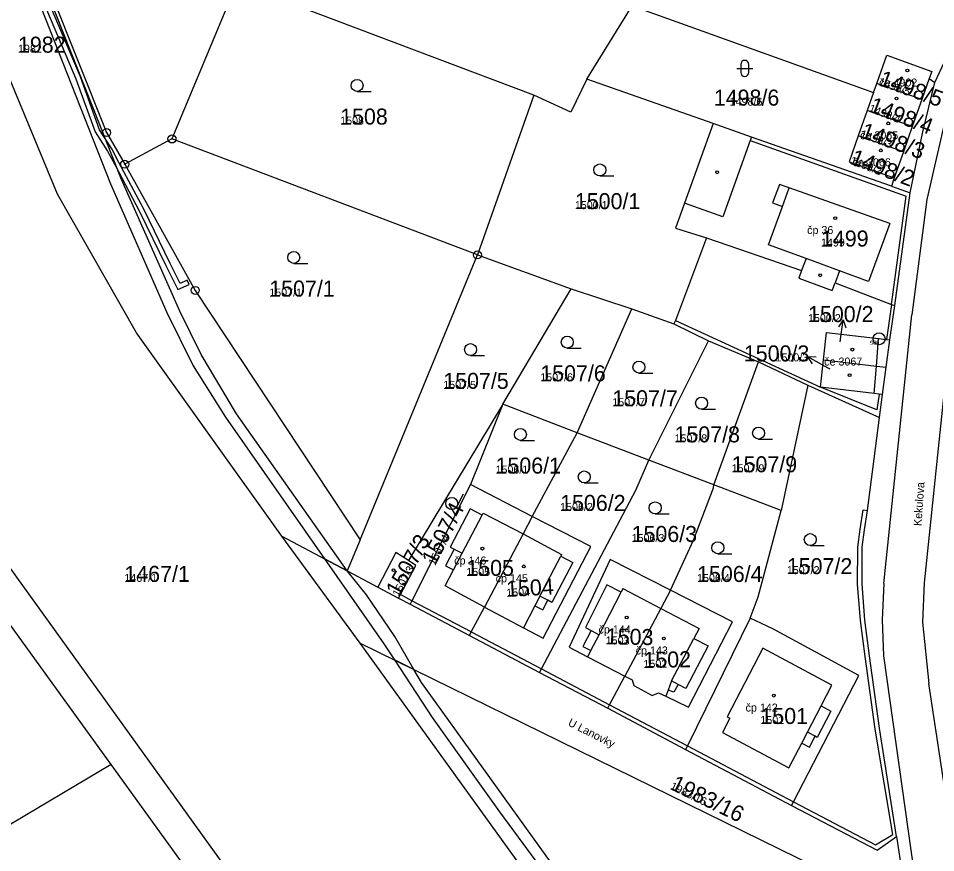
# Model space of a CAD drawing. Extents: x -763628 to -761565, y -976033 to -973833.
# Drawn here: x -762844 to -762729.4, y -975688.4 to -975584.1 of the extents above; entities that cross this region are included whole.
import ezdxf

# ---------------------------------------------------------------- set-up
doc = ezdxf.new("R2010")
doc.units = 0
for name, color, linetype in [('KN_cisla parcel 1000', 7, 'Continuous'), ('KN_cisla parcel 500', 7, 'Continuous'), ('KN_cisla parcel znacky', 7, 'Continuous'), ('KN_cisla popisna 500', 7, 'Continuous'), ('KN_hranice parcel', 7, 'Continuous'), ('KN_popisy', 7, 'Continuous'), ('KN_vecna bremena', 7, 'Continuous'), ('KN_vnitrni kresba parcel', 7, 'Continuous'), ('KN_znacky bodu BP', 7, 'Continuous'), ('KN_znacky budov', 7, 'Continuous'), ('KN_znacky kultur', 7, 'Continuous')]:
    doc.layers.add(name, color=color, linetype=linetype)

msp = doc.modelspace()

# ---------------------------------------------------------------- linework, layer by layer
at = {"layer": 'KN_cisla parcel znacky'}
for p, q in [((-762740.96, -975621.78), (-762741.54, -975622.62)), ((-762741.34, -975624.51), (-762740.96, -975621.78)), ((-762740.96, -975621.78), (-762740.63, -975622.75)), ((-762742.84, -975627.81), (-762745.47, -975626.36)), ((-762745.47, -975626.36), (-762744.35, -975626.4)), ((-762745.47, -975626.36), (-762744.83, -975627.28)), ((-762742.6, -975627.94), (-762742.84, -975627.81))]:
    msp.add_line(p, q, dxfattribs=at)
at = {"layer": 'KN_hranice parcel'}
for p, q in [((-762773, -975591.7), (-762767.32, -975582.5)), ((-762757.22, -975597.21), (-762773, -975591.7)), ((-762737.17, -975593.36), (-762736.77, -975592.23)), ((-762731.13, -975594.22), (-762736.77, -975592.23)), ((-762779.62, -975593.67), (-762786.67, -975613.65)), ((-762737.17, -975593.36), (-762737.96, -975595.6)), ((-762731.13, -975594.22), (-762732.33, -975597.59)), ((-762737.96, -975595.6), (-762739.08, -975598.78)), ((-762732.33, -975597.59), (-762737.96, -975595.6)), ((-762732.33, -975597.59), (-762733.45, -975600.77)), ((-762733.45, -975600.77), (-762739.08, -975598.78)), ((-762824.82, -975599.16), (-762830.73, -975602.32)), ((-762786.67, -975613.65), (-762824.82, -975599.16)), ((-762733.45, -975600.77), (-762734.59, -975604)), ((-762734.59, -975604), (-762734.95, -975605.07)), ((-762734.95, -975605.07), (-762732.6, -975605.9)), ((-762734.52, -975619.97), (-762732.6, -975605.9)), ((-762801.32, -975649.26), (-762786.67, -975613.65)), ((-762786.67, -975613.65), (-762774.97, -975617.89)), ((-762783.49, -975632.31), (-762774.97, -975617.89)), ((-762774.97, -975617.89), (-762767.36, -975620.39)), ((-762774.19, -975635.87), (-762767.36, -975620.39)), ((-762735.12, -975624.27), (-762734.52, -975619.97)), ((-762735.58, -975627.68), (-762735.12, -975624.27)), ((-762765.26, -975639.29), (-762757.79, -975624.4)), ((-762757.79, -975624.4), (-762751.56, -975627.01)), ((-762757.13, -975642.4), (-762751.56, -975627.01)), ((-762751.56, -975627.01), (-762745.39, -975629.93)), ((-762736.05, -975631.11), (-762735.58, -975627.68)), ((-762745.39, -975629.93), (-762748.73, -975645.61)), ((-762745.39, -975629.93), (-762736.44, -975633.97)), ((-762736.44, -975633.97), (-762736.05, -975631.11)), ((-762783.49, -975632.31), (-762795.29, -975651.85)), ((-762783.49, -975632.31), (-762787.53, -975642.34)), ((-762774.19, -975635.87), (-762783.49, -975632.31)), ((-762779.82, -975646.33), (-762774.19, -975635.87)), ((-762765.26, -975639.29), (-762774.19, -975635.87)), ((-762757.13, -975642.4), (-762765.26, -975639.29)), ((-762779.82, -975646.33), (-762787.53, -975642.34)), ((-762748.73, -975645.61), (-762757.13, -975642.4)), ((-762811.1, -975648.8), (-762802.92, -975653.15)), ((-762801.33, -975662.17), (-762811.1, -975648.8)), ((-762801.32, -975649.26), (-762802.92, -975653.15)), ((-762802.92, -975653.15), (-762799.12, -975655.17)), ((-762799.12, -975655.17), (-762796.51, -975656.55)), ((-762832.43, -975677.34), (-762847.47, -975656.53)), ((-762796.51, -975656.55), (-762795.06, -975657.31)), ((-762795.06, -975657.31), (-762787.66, -975661.21)), ((-762787.66, -975661.21), (-762778.9, -975665.83)), ((-762757.25, -975723.26), (-762801.33, -975662.17)), ((-762778.9, -975665.83), (-762770.38, -975670.32)), ((-762770.38, -975670.32), (-762760.65, -975675.46)), ((-762760.65, -975675.46), (-762747.41, -975682.45)), ((-762820.54, -975693.78), (-762832.43, -975677.34)), ((-762734.3, -975686.33), (-762732.8, -975696.41))]:
    msp.add_line(p, q, dxfattribs=at)
for points in [[(-762732.6, -975605.9), (-762731.03, -975598.28), (-762729.5, -975592.1), (-762728.34, -975589.62), (-762719.64, -975571.02), (-762714.08, -975552.67), (-762709.55, -975545.05), (-762703.62, -975531.5)], [(-762856.31, -975534.48), (-762857.3, -975537.42), (-762833, -975598.35), (-762830.73, -975602.32)], [(-762777.26, -975743.54), (-762778.83, -975742.17), (-762779.94, -975743.26), (-762853.85, -975640.55), (-762917.53, -975553.11), (-762915.39, -975552.59), (-762916.08, -975550.64)], [(-762811.1, -975648.8), (-762829.27, -975623.41), (-762839.12, -975606.05), (-762852.52, -975573.73)], [(-762779.62, -975593.67), (-762816.73, -975579.64), (-762824.82, -975599.16)], [(-762767.32, -975582.5), (-762760.11, -975585.08), (-762737.17, -975593.36)], [(-762736.77, -975592.23), (-762735.51, -975588.69), (-762729.9, -975590.73), (-762730.24, -975591.58), (-762731.13, -975594.22)], [(-762773, -975591.7), (-762774.99, -975595.79), (-762779.62, -975593.67)], [(-762757.22, -975597.21), (-762760.8, -975607.17), (-762761.92, -975610.3), (-762758.06, -975611.52), (-762746.16, -975615.6), (-762746.51, -975616.56), (-762742.33, -975618.1), (-762741.98, -975617.14), (-762734.95, -975619.83), (-762734.52, -975619.97)], [(-762734.95, -975605.07), (-762752.43, -975598.93), (-762757.22, -975597.21)], [(-762739.08, -975598.78), (-762740.22, -975602.01), (-762734.59, -975604)], [(-762830.73, -975602.32), (-762821.91, -975618.09), (-762801.32, -975649.26)], [(-762767.36, -975620.39), (-762762.11, -975622.25), (-762757.79, -975624.4)], [(-762743.43, -975626.77), (-762743.07, -975623.36), (-762736.54, -975624.11), (-762735.55, -975624.22), (-762735.12, -975624.27)], [(-762736.05, -975631.11), (-762736.49, -975631.06), (-762737.09, -975630.98), (-762743.79, -975630.18), (-762743.43, -975626.77)], [(-762743.43, -975626.77), (-762736.81, -975627.54), (-762735.58, -975627.68)], [(-762734.3, -975686.33), (-762736.42, -975672.82), (-762737.66, -975663.78), (-762738.26, -975659.29), (-762738.61, -975654.77), (-762738.59, -975650.16), (-762738.3, -975648.01), (-762737.95, -975645.58), (-762736.44, -975633.97)], [(-762778.9, -975665.83), (-762778.67, -975665.39), (-762766.88, -975643.06), (-762765.26, -975639.29)], [(-762787.53, -975642.34), (-762794.84, -975656.87), (-762795.06, -975657.31)], [(-762762.54, -975655.55), (-762759.68, -975649.32), (-762757.17, -975642.75), (-762757.13, -975642.4)], [(-762752.57, -975659.04), (-762751.6, -975656.39), (-762748.73, -975645.61)], [(-762779.82, -975646.33), (-762780.96, -975648.52), (-762785.76, -975657.66)], [(-762785.76, -975657.66), (-762780.89, -975660.25), (-762778.43, -975661.56), (-762772.51, -975650.11), (-762779.82, -975646.33)], [(-762795.29, -975651.85), (-762796.84, -975650.85), (-762799.12, -975655.17)], [(-762762.54, -975655.55), (-762770.06, -975651.71), (-762775.22, -975662.67), (-762772.91, -975663.87), (-762768.24, -975666.3)], [(-762796.51, -975656.55), (-762796.28, -975656.11), (-762794.35, -975652.46), (-762795.29, -975651.85)], [(-762768.24, -975666.3), (-762767.33, -975666.77), (-762767.13, -975667.49), (-762764.84, -975668.72), (-762764.03, -975668.37), (-762763.14, -975668.8), (-762760.31, -975670.18), (-762754.78, -975659.52), (-762762.54, -975655.55)], [(-762762.54, -975655.55), (-762763.75, -975657.84), (-762768.24, -975666.3)], [(-762787.66, -975661.21), (-762787.43, -975660.77), (-762785.76, -975657.66)], [(-762752.57, -975659.04), (-762760.42, -975675.01), (-762760.65, -975675.46)], [(-762747.41, -975682.45), (-762747.17, -975682.01), (-762739, -975666.23), (-762749.74, -975660.38), (-762752.57, -975659.04)], [(-762801.33, -975662.17), (-762794.59, -975665.48), (-762742.09, -975691.25)], [(-762770.38, -975670.32), (-762770.15, -975669.88), (-762768.24, -975666.3)], [(-762832.43, -975677.34), (-762846.27, -975685.61), (-762854.67, -975690.74), (-762863.95, -975696.17)], [(-762747.41, -975682.45), (-762736.73, -975688.07), (-762734.3, -975686.33)]]:
    msp.add_lwpolyline(points, dxfattribs=at)
at = {"layer": 'KN_vecna bremena'}
for points in [[(-762846.61, -975570.58), (-762843.88, -975575.86), (-762832.49, -975604.76), (-762825.46, -975620.86), (-762822.16, -975627.52), (-762818.12, -975633.95), (-762805.77, -975651.64), (-762802.92, -975653.15), (-762816.74, -975633.5), (-762821.17, -975626.08), (-762823.86, -975620.67), (-762831.14, -975604.24), (-762841.95, -975576.87), (-762843.4, -975573.8), (-762848.49, -975565.08)], [(-762844.93, -975571.69), (-762843.04, -975576.63), (-762840.81, -975582.19), (-762836.83, -975591.63), (-762834.41, -975598.27), (-762832.86, -975600.68), (-762831.96, -975602.36), (-762828.86, -975608.23), (-762825.6, -975614.97), (-762824.08, -975617.99), (-762822.68, -975617.35), (-762822.93, -975616.8), (-762823.8, -975617.21), (-762825.06, -975614.71), (-762828.32, -975607.95), (-762831.44, -975602.08), (-762832.34, -975600.38), (-762833.87, -975598.01), (-762836.27, -975591.41), (-762840.25, -975581.97), (-762842.48, -975576.41), (-762844.51, -975571.09)]]:
    msp.add_lwpolyline(points, dxfattribs=at)
for points in [[(-762797.03, -975664.28), (-762794.59, -975665.48), (-762797, -975661.33), (-762800.52, -975656.14), (-762802.92, -975653.15), (-762805.77, -975651.64), (-762798.35, -975662.26)], [(-762797.03, -975664.28), (-762792.31, -975671.49), (-762783.9, -975683.27), (-762759.91, -975715.83), (-762757.15, -975720.53), (-762756.64, -975723.08), (-762756.93, -975723.71), (-762756.65, -975724.13), (-762755.82, -975722.26), (-762755.51, -975721.15), (-762756.19, -975719.29), (-762759.18, -975714.08), (-762778.08, -975688.75), (-762793.65, -975667.11), (-762794.59, -975665.48)]]:
    msp.add_lwpolyline(points, close=True, dxfattribs=at)
at = {"layer": 'KN_vnitrni kresba parcel'}
for p, q in [((-762726.73, -975590.15), (-762730.51, -975606.74)), ((-762730.24, -975591.58), (-762729.5, -975592.1)), ((-762752.43, -975598.93), (-762752.58, -975599.35)), ((-762752.58, -975599.35), (-762756.02, -975608.91)), ((-762752.58, -975599.35), (-762733.11, -975606.29)), ((-762748.93, -975604.84), (-762749.78, -975607.14)), ((-762747.71, -975605.27), (-762748.93, -975604.84)), ((-762748.53, -975607.58), (-762747.71, -975605.27)), ((-762735.13, -975609.74), (-762747.71, -975605.27)), ((-762734.95, -975619.83), (-762733.11, -975606.29)), ((-762730.51, -975606.74), (-762732.39, -975621.12)), ((-762756.02, -975608.91), (-762760.8, -975607.17)), ((-762750.31, -975612.37), (-762748.53, -975607.58)), ((-762749.78, -975607.14), (-762748.53, -975607.58)), ((-762735.13, -975609.74), (-762737.79, -975616.98)), ((-762758.06, -975611.52), (-762761.93, -975621.84)), ((-762745.6, -975614.1), (-762750.31, -975612.37)), ((-762745.6, -975614.1), (-762746.16, -975615.6)), ((-762741.43, -975615.64), (-762745.6, -975614.1)), ((-762741.43, -975615.64), (-762741.98, -975617.14)), ((-762737.79, -975616.98), (-762741.43, -975615.64)), ((-762734.95, -975619.83), (-762735.55, -975624.22)), ((-762761.93, -975621.84), (-762762.11, -975622.25)), ((-762761.93, -975621.84), (-762743.79, -975630.18)), ((-762735.88, -975654.72), (-762732.39, -975621.12)), ((-762727.34, -975621.05), (-762730.83, -975654.64)), ((-762736.81, -975627.54), (-762736.54, -975624.11)), ((-762737.09, -975630.98), (-762736.81, -975627.54)), ((-762736.76, -975633.02), (-762743.79, -975630.18)), ((-762736.49, -975631.06), (-762736.76, -975633.02)), ((-762787.58, -975645.39), (-762790.07, -975650.16)), ((-762786.07, -975646.17), (-762787.58, -975645.39)), ((-762786.07, -975646.17), (-762785.94, -975645.93)), ((-762785.94, -975645.93), (-762780.96, -975648.52)), ((-762738.84, -975647.94), (-762738.49, -975645.5)), ((-762738.49, -975645.5), (-762737.95, -975645.58)), ((-762788.55, -975650.95), (-762786.07, -975646.17)), ((-762739.14, -975650.17), (-762738.84, -975647.94)), ((-762780.96, -975648.52), (-762776.14, -975651.08)), ((-762789.55, -975650.43), (-762790.63, -975652.5)), ((-762790.07, -975650.16), (-762789.55, -975650.43)), ((-762789.55, -975650.43), (-762788.55, -975650.95)), ((-762739.16, -975654.79), (-762739.14, -975650.17)), ((-762789.63, -975653.03), (-762788.55, -975650.95)), ((-762778.85, -975656.31), (-762776.26, -975651.31)), ((-762776.14, -975651.08), (-762776.26, -975651.31)), ((-762776.26, -975651.31), (-762774.76, -975652.09)), ((-762790.63, -975652.5), (-762789.63, -975653.03)), ((-762774.76, -975652.09), (-762777.36, -975657.09)), ((-762790.7, -975655.03), (-762789.63, -975653.03)), ((-762785.76, -975657.66), (-762790.7, -975655.03)), ((-762770.51, -975654.88), (-762773.17, -975660.23)), ((-762768.72, -975655.81), (-762770.51, -975654.88)), ((-762738.81, -975659.34), (-762739.16, -975654.79)), ((-762735.88, -975654.72), (-762736.1, -975659.26)), ((-762730.83, -975654.64), (-762731.05, -975659.56)), ((-762794.84, -975656.87), (-762796.28, -975656.11)), ((-762778.85, -975656.31), (-762779.47, -975657.51)), ((-762777.87, -975656.82), (-762778.85, -975656.31)), ((-762771.47, -975661.12), (-762768.72, -975655.81)), ((-762768.48, -975655.35), (-762768.72, -975655.81)), ((-762768.48, -975655.35), (-762763.75, -975657.84)), ((-762787.43, -975660.77), (-762794.84, -975656.87)), ((-762779.47, -975657.51), (-762780.89, -975660.25)), ((-762779.47, -975657.51), (-762778.49, -975658.01)), ((-762778.49, -975658.01), (-762777.87, -975656.82)), ((-762777.36, -975657.09), (-762777.87, -975656.82)), ((-762763.75, -975657.84), (-762758.97, -975660.35)), ((-762738.21, -975663.85), (-762738.81, -975659.34)), ((-762736.1, -975659.26), (-762735.92, -975663.75)), ((-762731.05, -975659.56), (-762730.28, -975667.23)), ((-762787.43, -975660.77), (-762778.67, -975665.39)), ((-762772.44, -975660.61), (-762773.48, -975662.58)), ((-762773.17, -975660.23), (-762772.44, -975660.61)), ((-762772.44, -975660.61), (-762771.47, -975661.12)), ((-762758.97, -975660.35), (-762759.62, -975661.59)), ((-762772.5, -975663.09), (-762771.47, -975661.12)), ((-762762.41, -975666.9), (-762759.62, -975661.59)), ((-762759.62, -975661.59), (-762757.84, -975662.52)), ((-762773.48, -975662.58), (-762772.5, -975663.09)), ((-762772.5, -975663.09), (-762772.91, -975663.87)), ((-762757.84, -975662.52), (-762760.62, -975667.84)), ((-762751.01, -975662.82), (-762755.46, -975671.4)), ((-762742.39, -975667.42), (-762751.01, -975662.82)), ((-762736.96, -975672.91), (-762738.21, -975663.85)), ((-762735.92, -975663.75), (-762729.86, -975706.89)), ((-762778.67, -975665.39), (-762770.15, -975669.88)), ((-762762.41, -975666.9), (-762762.85, -975668.04)), ((-762761.6, -975667.33), (-762762.41, -975666.9)), ((-762761.6, -975667.33), (-762762.11, -975668.31)), ((-762760.62, -975667.84), (-762761.6, -975667.33)), ((-762743.73, -975670.01), (-762742.39, -975667.42)), ((-762722.28, -975720.1), (-762730.28, -975667.23)), ((-762762.85, -975668.04), (-762763.14, -975668.8)), ((-762762.11, -975668.31), (-762762.85, -975668.04)), ((-762770.15, -975669.88), (-762760.42, -975675.01)), ((-762745.44, -975673.31), (-762743.73, -975670.01)), ((-762743.73, -975670.01), (-762742.49, -975670.66)), ((-762742.49, -975670.66), (-762744.2, -975673.95)), ((-762755.12, -975671.57), (-762756.06, -975673.34)), ((-762755.46, -975671.4), (-762755.12, -975671.57)), ((-762756.06, -975673.34), (-762747.74, -975677.75)), ((-762746.14, -975674.66), (-762745.44, -975673.31)), ((-762744.46, -975673.81), (-762745.44, -975673.31)), ((-762734.76, -975686.09), (-762736.96, -975672.91)), ((-762747.74, -975677.75), (-762746.14, -975674.66)), ((-762746.14, -975674.66), (-762745.16, -975675.17)), ((-762745.16, -975675.17), (-762744.46, -975673.81)), ((-762744.2, -975673.95), (-762744.46, -975673.81)), ((-762760.42, -975675.01), (-762747.17, -975682.01)), ((-762747.17, -975682.01), (-762736.94, -975687.4)), ((-762736.94, -975687.4), (-762734.76, -975686.09))]:
    msp.add_line(p, q, dxfattribs=at)
at = {"layer": 'KN_znacky bodu BP'}
for centre, radius in [((-762833, -975598.35), 0.5), ((-762833, -975598.35), 0.0303), ((-762824.82, -975599.16), 0.5), ((-762824.82, -975599.16), 0.0303), ((-762830.73, -975602.32), 0.5), ((-762830.73, -975602.32), 0.0303), ((-762786.67, -975613.65), 0.5), ((-762786.67, -975613.65), 0.0303), ((-762821.91, -975618.09), 0.5), ((-762821.91, -975618.09), 0.0303), ((-762736.49, -975624.13), 0.75), ((-762736.49, -975624.13), 0.03)]:
    msp.add_circle(centre, radius, dxfattribs=at)
at = {"layer": 'KN_znacky budov'}
for centre in [(-762732.95, -975590.61), (-762734.3, -975594.11), (-762735.33, -975597.21), (-762736.26, -975600.58), (-762756.71, -975603.32), (-762741.95, -975609.05), (-762743.84, -975616.2), (-762739.82, -975625.49), (-762740.16, -975628.69), (-762786.04, -975650.36), (-762797.15, -975653.05), (-762780.86, -975652.58), (-762768.01, -975658.98), (-762763.37, -975661.6), (-762749.64, -975668.74)]:
    msp.add_circle(centre, 0.175, dxfattribs=at)
at = {"layer": 'KN_znacky kultur'}
for p, q in [((-762753.76, -975589.83), (-762753.76, -975590.83)), ((-762752.76, -975590.83), (-762752.76, -975589.83)), ((-762754.26, -975590.33), (-762752.26, -975590.33)), ((-762801.69, -975593.21), (-762799.94, -975593.21)), ((-762771.37, -975603.78), (-762769.62, -975603.78)), ((-762809.61, -975614.71), (-762807.86, -975614.71)), ((-762775.44, -975625.3), (-762773.69, -975625.3)), ((-762787.52, -975626.24), (-762785.77, -975626.24)), ((-762766.48, -975628.42), (-762764.73, -975628.42)), ((-762758.65, -975632.93), (-762756.9, -975632.93)), ((-762781.3, -975636.83), (-762779.55, -975636.83)), ((-762751.53, -975636.67), (-762749.78, -975636.67)), ((-762773.31, -975642.15), (-762771.56, -975642.15)), ((-762789.21, -975645.07), (-762788.39, -975643.53)), ((-762764.46, -975646.02), (-762762.71, -975646.02)), ((-762745.08, -975649.99), (-762743.33, -975649.99)), ((-762756.63, -975651), (-762754.88, -975651))]:
    msp.add_line(p, q, dxfattribs=at)
for centre in [(-762801.69, -975592.46), (-762771.37, -975603.03), (-762809.61, -975613.96), (-762775.44, -975624.55), (-762787.52, -975625.49), (-762766.48, -975627.67), (-762758.65, -975632.18), (-762781.3, -975636.08), (-762751.53, -975635.92), (-762773.31, -975641.4), (-762789.87, -975644.72), (-762764.46, -975645.27), (-762745.08, -975649.24), (-762756.63, -975650.25)]:
    msp.add_circle(centre, 0.75, dxfattribs=at)
for centre, start, end in [((-762753.26, -975589.83), 0, 180), ((-762753.26, -975590.83), 180, 359.9879)]:
    msp.add_arc(centre, 0.5, start, end, dxfattribs=at)

# ---------------------------------------------------------------- texts
at = {"layer": 'KN_cisla parcel 1000'}
for s, p in [('1982', (-762844.06, -975588.37)), ('1498/6', (-762757.13, -975594.99)), ('1508', (-762803.81, -975597.36)), ('1500/1', (-762774.49, -975607.93)), ('1499', (-762743.74, -975612.6)), ('1507/1', (-762812.67, -975618.86)), ('1500/2', (-762745.36, -975622.04)), ('1500/3', (-762753.38, -975626.96)), ('1507/6', (-762778.81, -975629.45)), ('1507/5', (-762790.93, -975630.39)), ('1507/7', (-762769.81, -975632.57)), ('1507/8', (-762762.04, -975637.08)), ('1506/1', (-762784.4, -975640.98)), ('1507/9', (-762754.9, -975640.82)), ('1506/2', (-762776.33, -975645.65)), ('1506/3', (-762767.4, -975649.53)), ('1505', (-762788.05, -975653.77)), ('1507/2', (-762748.01, -975653.55)), ('1467/1', (-762830.77, -975654.52)), ('1506/4', (-762759.22, -975654.53)), ('1501', (-762751.31, -975672.28))]:
    msp.add_text(s, height=2, dxfattribs=at).set_placement(p)
for s, rotation, p in [('1498/5', 340, (-762736.63, -975592.4)), ('1498/4', 339, (-762737.85, -975595.71)), ('1498/3', 340, (-762738.92, -975598.93)), ('1498/2', 339, (-762740.2, -975602.23)), ('1507/4', 63, (-762791.95, -975652.56)), ('1507/3', 61, (-762796.48, -975656.46)), ('1504', 3, (-762783.03, -975656.4)), ('1503', 359, (-762770.64, -975662.32)), ('1502', 1, (-762765.91, -975665.28)), ('1983/16', 334, (-762762.67, -975680.39))]:
    msp.add_text(s, height=2, rotation=rotation, dxfattribs=at).set_placement(p)
at = {"layer": 'KN_cisla parcel 500'}
for s, p in [('1982', (-762844.06, -975588.37)), ('1498/6', (-762755.15, -975594.99)), ('1508', (-762803.81, -975597.36)), ('1500/1', (-762774.49, -975607.93)), ('1499', (-762743.74, -975612.6)), ('1507/1', (-762812.67, -975618.86)), ('1500/2', (-762745.36, -975622.04)), ('1500/3', (-762749.42, -975626.96)), ('1507/6', (-762778.81, -975629.45)), ('1507/5', (-762790.93, -975630.39)), ('1507/7', (-762769.81, -975632.57)), ('1507/8', (-762762.04, -975637.08)), ('1506/1', (-762784.4, -975640.98)), ('1507/9', (-762754.9, -975640.82)), ('1506/2', (-762776.33, -975645.65)), ('1506/3', (-762767.4, -975649.53)), ('1505', (-762788.05, -975653.77)), ('1507/2', (-762748.01, -975653.55)), ('1467/1', (-762830.77, -975654.52)), ('1506/4', (-762759.22, -975654.53)), ('1501', (-762751.31, -975672.28))]:
    msp.add_text(s, height=1, dxfattribs=at).set_placement(p)
for s, rotation, p in [('1498/5', 340, (-762736.63, -975592.4)), ('1498/4', 339, (-762737.85, -975595.71)), ('1498/3', 340, (-762738.92, -975598.93)), ('1498/2', 339, (-762740.2, -975602.23)), ('1507/4', 63, (-762791.95, -975652.56)), ('1507/3', 61, (-762796.48, -975656.46)), ('1504', 3, (-762783.03, -975656.4)), ('1503', 359, (-762770.64, -975662.32)), ('1502', 1, (-762765.91, -975665.28)), ('1983/16', 334, (-762762.67, -975680.39))]:
    msp.add_text(s, height=1, rotation=rotation, dxfattribs=at).set_placement(p)
at = {"layer": 'KN_cisla popisna 500'}
for s, p in [('če 4902', (-762736.47, -975592.6)), ('če 3065', (-762738.85, -975599.2)), ('če 3066', (-762739.78, -975602.57)), ('čp 36', (-762745.47, -975611.04)), ('če 3067', (-762743.34, -975627.48)), ('čp 146', (-762789.56, -975652.35)), ('čp 145', (-762784.38, -975654.57)), ('čp 144', (-762771.53, -975660.97)), ('čp 143', (-762766.89, -975663.59)), ('čp 142', (-762753.16, -975670.73))]:
    msp.add_text(s, height=1, dxfattribs=at).set_placement(p)
at = {"layer": 'KN_popisy'}
for s, rotation, p in [('Kekulova', 86, (-762731.19, -975647.56)), ('U Lanovky', 333, (-762775.43, -975672.43))]:
    msp.add_text(s, height=1, rotation=rotation, dxfattribs=at).set_placement(p)
at = {"layer": 'KN_znacky bodu BP'}
msp.add_text('509', height=0.5, dxfattribs=at).set_placement((-762737.61, -975624.88))

doc.saveas('drawing.dxf')
